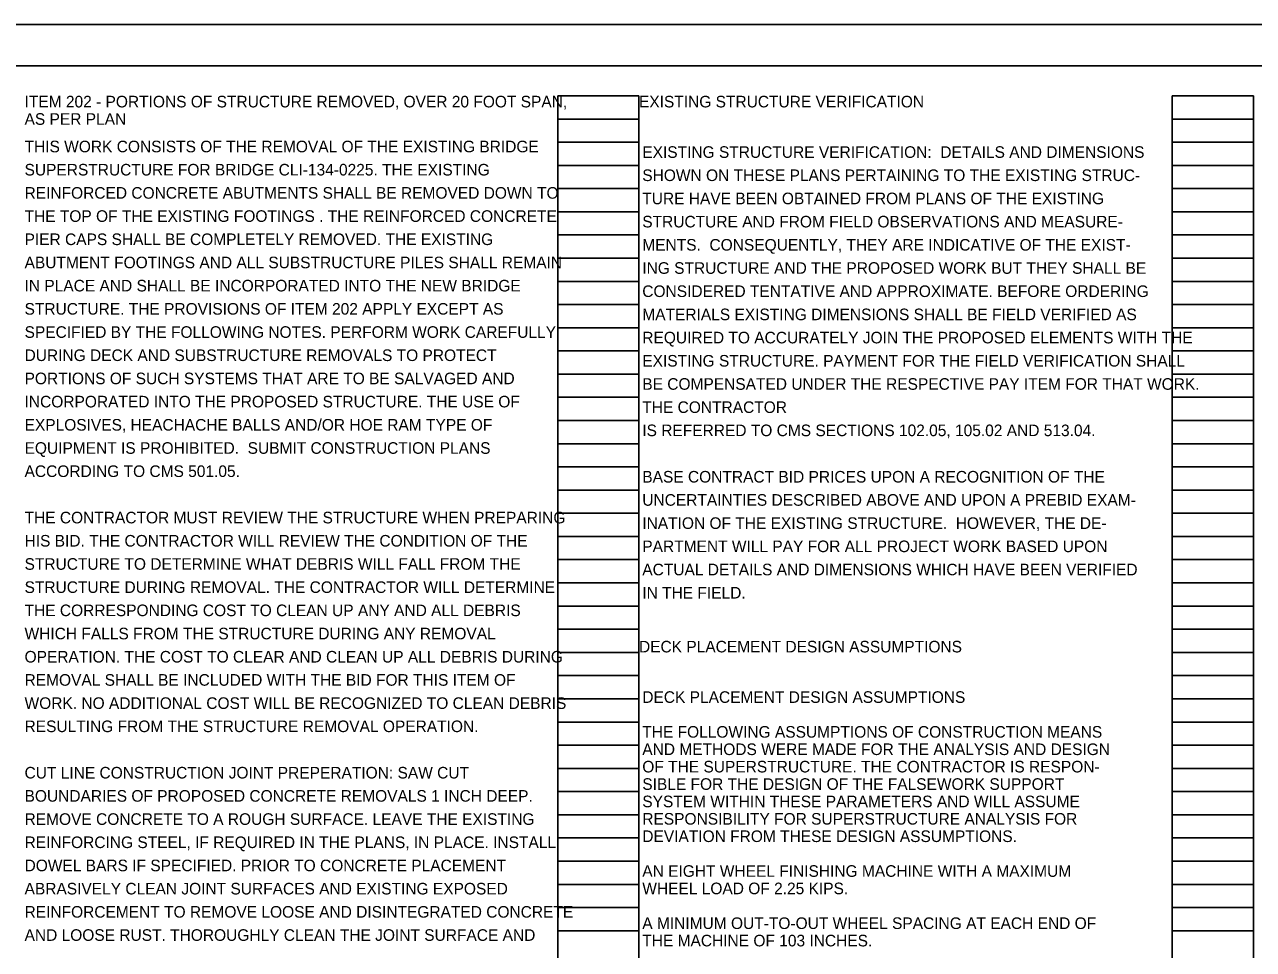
# Model space of a CAD drawing. Extents: x 0 to 48.4, y -19.4 to 22.
# Drawn here: x 9.82 to 24.66, y 10.83 to 22 of the extents above; entities that cross this region are included whole.
import ezdxf

# ---------------------------------------------------------------- set-up
doc = ezdxf.new("R2010")
doc.units = 0
for name, color, linetype in [('BR_P_Gen_Text', 7, 'Continuous'), ('SH_Border', 7, 'Continuous'), ('SH_Cut_Line', 7, 'Continuous'), ('SH_Data', 7, 'Continuous'), ('SH_Text', 7, 'Continuous')]:
    doc.layers.add(name, color=color, linetype=linetype)

msp = doc.modelspace()

# ---------------------------------------------------------------- linework, layer by layer
at = {"layer": 'SH_Border'}
msp.add_lwpolyline([(1.5, 21.5), (33.5, 21.5), (33.5, 0.5), (1.5, 0.5)], close=True, dxfattribs=at)
at = {"layer": 'SH_Cut_Line'}
msp.add_lwpolyline([(0, 0), (34, 0), (34, 22), (0, 22)], close=True, dxfattribs=at)
at = {"layer": 'SH_Data'}
for p, q in [((16.26, 0.98), (16.26, 21.14)), ((16.26, 21.14), (17.24, 21.14)), ((17.24, 0.98), (17.24, 21.14)), ((23.68, 0.98), (23.68, 21.14)), ((23.68, 21.14), (24.66, 21.14)), ((24.66, 0.98), (24.66, 21.14)), ((16.26, 20.86), (17.24, 20.86)), ((23.68, 20.86), (24.66, 20.86)), ((16.26, 20.58), (17.24, 20.58)), ((23.68, 20.58), (24.66, 20.58)), ((16.26, 20.3), (17.24, 20.3)), ((23.68, 20.3), (24.66, 20.3)), ((16.26, 20.02), (17.24, 20.02)), ((23.68, 20.02), (24.66, 20.02)), ((16.26, 19.74), (17.24, 19.74)), ((23.68, 19.74), (24.66, 19.74)), ((16.26, 19.46), (17.24, 19.46)), ((23.68, 19.46), (24.66, 19.46)), ((16.26, 19.18), (17.24, 19.18)), ((23.68, 19.18), (24.66, 19.18)), ((16.26, 18.9), (17.24, 18.9)), ((23.68, 18.9), (24.66, 18.9)), ((16.26, 18.62), (17.24, 18.62)), ((23.68, 18.62), (24.66, 18.62)), ((16.26, 18.34), (17.24, 18.34)), ((23.68, 18.34), (24.66, 18.34)), ((16.26, 18.06), (17.24, 18.06)), ((23.68, 18.06), (24.66, 18.06)), ((16.26, 17.78), (17.24, 17.78)), ((23.68, 17.78), (24.66, 17.78)), ((16.26, 17.5), (17.24, 17.5)), ((23.68, 17.5), (24.66, 17.5)), ((16.26, 17.22), (17.24, 17.22)), ((23.68, 17.22), (24.66, 17.22)), ((16.26, 16.94), (17.24, 16.94)), ((23.68, 16.94), (24.66, 16.94)), ((16.26, 16.66), (17.24, 16.66)), ((23.68, 16.66), (24.66, 16.66)), ((16.26, 16.38), (17.24, 16.38)), ((23.68, 16.38), (24.66, 16.38)), ((16.26, 16.1), (17.24, 16.1)), ((23.68, 16.1), (24.66, 16.1)), ((16.26, 15.82), (17.24, 15.82)), ((23.68, 15.82), (24.66, 15.82)), ((16.26, 15.54), (17.24, 15.54)), ((23.68, 15.54), (24.66, 15.54)), ((16.26, 15.26), (17.24, 15.26)), ((23.68, 15.26), (24.66, 15.26)), ((16.26, 14.98), (17.24, 14.98)), ((23.68, 14.98), (24.66, 14.98)), ((16.26, 14.7), (17.24, 14.7)), ((23.68, 14.7), (24.66, 14.7)), ((16.26, 14.42), (17.24, 14.42)), ((23.68, 14.42), (24.66, 14.42)), ((16.26, 14.14), (17.24, 14.14)), ((23.68, 14.14), (24.66, 14.14)), ((16.26, 13.86), (17.24, 13.86)), ((23.68, 13.86), (24.66, 13.86)), ((16.26, 13.58), (17.24, 13.58)), ((23.68, 13.58), (24.66, 13.58)), ((16.26, 13.3), (17.24, 13.3)), ((23.68, 13.3), (24.66, 13.3)), ((16.26, 13.02), (17.24, 13.02)), ((23.68, 13.02), (24.66, 13.02)), ((16.26, 12.74), (17.24, 12.74)), ((23.68, 12.74), (24.66, 12.74)), ((16.26, 12.46), (17.24, 12.46)), ((23.68, 12.46), (24.66, 12.46)), ((16.26, 12.18), (17.24, 12.18)), ((23.68, 12.18), (24.66, 12.18)), ((16.26, 11.9), (17.24, 11.9)), ((23.68, 11.9), (24.66, 11.9)), ((16.26, 11.62), (17.24, 11.62)), ((23.68, 11.62), (24.66, 11.62)), ((16.26, 11.34), (17.24, 11.34)), ((23.68, 11.34), (24.66, 11.34)), ((16.26, 11.06), (17.24, 11.06)), ((23.68, 11.06), (24.66, 11.06))]:
    msp.add_line(p, q, dxfattribs=at)

# ---------------------------------------------------------------- texts
at = {"layer": 'BR_P_Gen_Text'}
for s, p in [('ITEM 202 - PORTIONS OF STRUCTURE REMOVED, OVER 20 FOOT SPAN, ', (9.82, 21)), ('EXISTING STRUCTURE VERIFICATION', (17.24, 21)), ('AS PER PLAN', (9.82, 20.79)), ('THIS WORK CONSISTS OF THE REMOVAL OF THE EXISTING BRIDGE ', (9.82, 20.458)), ('SUPERSTRUCTURE FOR BRIDGE CLI-134-0225. THE EXISTING ', (9.82, 20.178)), ('REINFORCED CONCRETE ABUTMENTS SHALL BE REMOVED DOWN TO ', (9.82, 19.898)), ('THE TOP OF THE EXISTING FOOTINGS . THE REINFORCED CONCRETE ', (9.82, 19.618)), ('PIER CAPS SHALL BE COMPLETELY REMOVED. THE EXISTING ', (9.82, 19.338)), ('ABUTMENT FOOTINGS AND ALL SUBSTRUCTURE PILES SHALL REMAIN ', (9.82, 19.058)), ('IN PLACE AND SHALL BE INCORPORATED INTO THE NEW BRIDGE ', (9.82, 18.778)), ('STRUCTURE. THE PROVISIONS OF ITEM 202 APPLY EXCEPT AS ', (9.82, 18.498)), ('SPECIFIED BY THE FOLLOWING NOTES. PERFORM WORK CAREFULLY ', (9.82, 18.218)), ('DURING DECK AND SUBSTRUCTURE REMOVALS TO PROTECT ', (9.82, 17.938)), ('PORTIONS OF SUCH SYSTEMS THAT ARE TO BE SALVAGED AND ', (9.82, 17.658)), ('INCORPORATED INTO THE PROPOSED STRUCTURE. THE USE OF ', (9.82, 17.378)), ('EXPLOSIVES, HEACHACHE BALLS AND/OR HOE RAM TYPE OF ', (9.82, 17.098)), ('EQUIPMENT IS PROHIBITED.  SUBMIT CONSTRUCTION PLANS ', (9.82, 16.818)), ('ACCORDING TO CMS 501.05.', (9.82, 16.538)), ('THE CONTRACTOR MUST REVIEW THE STRUCTURE WHEN PREPARING ', (9.82, 15.978)), ('HIS BID. THE CONTRACTOR WILL REVIEW THE CONDITION OF THE ', (9.82, 15.698)), ('STRUCTURE TO DETERMINE WHAT DEBRIS WILL FALL FROM THE ', (9.82, 15.418)), ('STRUCTURE DURING REMOVAL. THE CONTRACTOR WILL DETERMINE ', (9.82, 15.138)), ('THE CORRESPONDING COST TO CLEAN UP ANY AND ALL DEBRIS ', (9.82, 14.858)), ('WHICH FALLS FROM THE STRUCTURE DURING ANY REMOVAL ', (9.82, 14.578)), ('DECK PLACEMENT DESIGN ASSUMPTIONS', (17.24, 14.42)), ('OPERATION. THE COST TO CLEAR AND CLEAN UP ALL DEBRIS DURING ', (9.82, 14.298)), ('REMOVAL SHALL BE INCLUDED WITH THE BID FOR THIS ITEM OF ', (9.82, 14.018)), ('WORK. NO ADDITIONAL COST WILL BE RECOGNIZED TO CLEAN DEBRIS ', (9.82, 13.738)), ('RESULTING FROM THE STRUCTURE REMOVAL OPERATION. ', (9.82, 13.458)), ('CUT LINE CONSTRUCTION JOINT PREPERATION: SAW CUT ', (9.82, 12.898)), ('BOUNDARIES OF PROPOSED CONCRETE REMOVALS 1 INCH DEEP. ', (9.82, 12.618)), ('REMOVE CONCRETE TO A ROUGH SURFACE. LEAVE THE EXISTING ', (9.82, 12.338)), ('REINFORCING STEEL, IF REQUIRED IN THE PLANS, IN PLACE. INSTALL ', (9.82, 12.058)), ('DOWEL BARS IF SPECIFIED. PRIOR TO CONCRETE PLACEMENT ', (9.82, 11.778)), ('ABRASIVELY CLEAN JOINT SURFACES AND EXISTING EXPOSED ', (9.82, 11.498)), ('REINFORCEMENT TO REMOVE LOOSE AND DISINTEGRATED CONCRETE ', (9.82, 11.218)), ('AND LOOSE RUST. THOROUGHLY CLEAN THE JOINT SURFACE AND ', (9.82, 10.938))]:
    msp.add_text(s, height=0.14, dxfattribs=at).set_placement(p)
at = {"layer": 'SH_Text'}
for s, p in [('EXISTING STRUCTURE VERIFICATION:  DETAILS AND DIMENSIONS', (17.28, 20.391)), ('SHOWN ON THESE PLANS PERTAINING TO THE EXISTING STRUC-', (17.28, 20.111)), ('TURE HAVE BEEN OBTAINED FROM PLANS OF THE EXISTING', (17.28, 19.831)), ('STRUCTURE AND FROM FIELD OBSERVATIONS AND MEASURE-', (17.28, 19.551)), ('MENTS.  CONSEQUENTLY, THEY ARE INDICATIVE OF THE EXIST-', (17.28, 19.271)), ('ING STRUCTURE AND THE PROPOSED WORK BUT THEY SHALL BE', (17.28, 18.991)), ('CONSIDERED TENTATIVE AND APPROXIMATE. BEFORE ORDERING ', (17.28, 18.711)), ('MATERIALS EXISTING DIMENSIONS SHALL BE FIELD VERIFIED AS ', (17.28, 18.431)), ('REQUIRED TO ACCURATELY JOIN THE PROPOSED ELEMENTS WITH THE ', (17.28, 18.151)), ('EXISTING STRUCTURE. PAYMENT FOR THE FIELD VERIFICATION SHALL ', (17.28, 17.871)), ('BE COMPENSATED UNDER THE RESPECTIVE PAY ITEM FOR THAT WORK. ', (17.28, 17.591)), ('THE CONTRACTOR', (17.28, 17.311)), ('IS REFERRED TO CMS SECTIONS 102.05, 105.02 AND 513.04.', (17.28, 17.031)), ('BASE CONTRACT BID PRICES UPON A RECOGNITION OF THE', (17.28, 16.471)), ('UNCERTAINTIES DESCRIBED ABOVE AND UPON A PREBID EXAM-', (17.28, 16.191)), ('INATION OF THE EXISTING STRUCTURE.  HOWEVER, THE DE-', (17.28, 15.911)), ('PARTMENT WILL PAY FOR ALL PROJECT WORK BASED UPON', (17.28, 15.631)), ('ACTUAL DETAILS AND DIMENSIONS WHICH HAVE BEEN VERIFIED', (17.28, 15.351)), ('IN THE FIELD.', (17.28, 15.071)), ('DECK PLACEMENT DESIGN ASSUMPTIONS', (17.28, 13.811)), ('THE FOLLOWING ASSUMPTIONS OF CONSTRUCTION MEANS', (17.28, 13.391)), ('AND METHODS WERE MADE FOR THE ANALYSIS AND DESIGN', (17.28, 13.181)), ('OF THE SUPERSTRUCTURE. THE CONTRACTOR IS RESPON-', (17.28, 12.971)), ('SIBLE FOR THE DESIGN OF THE FALSEWORK SUPPORT', (17.28, 12.761)), ('SYSTEM WITHIN THESE PARAMETERS AND WILL ASSUME', (17.28, 12.551)), ('RESPONSIBILITY FOR SUPERSTRUCTURE ANALYSIS FOR', (17.28, 12.341)), ('DEVIATION FROM THESE DESIGN ASSUMPTIONS.', (17.28, 12.131)), ('AN EIGHT WHEEL FINISHING MACHINE WITH A MAXIMUM', (17.28, 11.711)), ('WHEEL LOAD OF 2.25 KIPS.', (17.28, 11.501)), ('A MINIMUM OUT-TO-OUT WHEEL SPACING AT EACH END OF', (17.28, 11.081)), ('THE MACHINE OF 103 INCHES.', (17.28, 10.871))]:
    msp.add_text(s, height=0.14, dxfattribs=at).set_placement(p)

doc.saveas('drawing.dxf')
